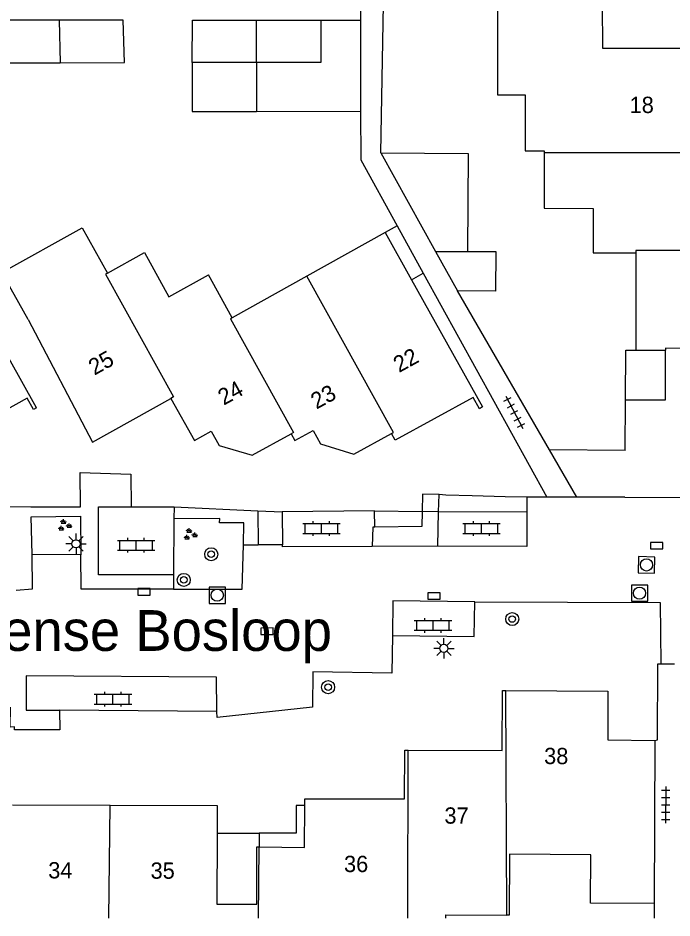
# Model space of a CAD drawing. Extents: x 128999 to 131010, y 395498 to 399007.
# Drawn here: x 130734 to 130774.1, y 395500 to 395555.2 of the extents above; entities that cross this region are included whole.
import ezdxf

# ---------------------------------------------------------------- set-up
doc = ezdxf.new("R2010")
doc.units = 0
for name, color, linetype in [('gg-afsc-erfafscheiding', 7, 'Continuous'), ('gg-anno-huisnummerreeks BGT', 7, 'Continuous'), ('gg-anno-openbare ruimte label', 7, 'Continuous'), ('gg-bbg-gedigitaliseerde bebouwing', 7, 'Continuous'), ('gg-bbg-gedigitaliseerde bijgebouw', 7, 'Continuous'), ('gg-bbg-hoofdgebouw', 7, 'Continuous'), ('gg-bbg-luifel en loopbrug', 7, 'Continuous'), ('gg-bbg-tussenscheiding', 7, 'Continuous'), ('gg-knt-verharding', 7, 'Continuous'), ('gg-knt-verharding nz', 7, 'Continuous'), ('gt-grn-groengrens', 7, 'Continuous'), ('gt-grn-weggrens', 7, 'Continuous'), ('gt-symb-boom', 7, 'Continuous'), ('gt-symb-groenvak', 7, 'Continuous'), ('gt-symb-klinker verharding', 7, 'Continuous'), ('gt-symb-kolk', 7, 'Continuous'), ('gt-symb-lichtmast', 7, 'Continuous'), ('gt-symb-rioolschacht', 7, 'Continuous'), ('gt-symb-tegel verharding', 7, 'Continuous')]:
    doc.layers.add(name, color=color, linetype=linetype)

# ---------------------------------------------------------------- blocks, each defined once
blk = doc.blocks.new('gt0-GRVAK')
at = {"layer": 'gt-symb-groenvak'}
for p, q in [((-0.11, 0.189), (-0.228, 0.24)), ((-0.182, 0.153), (0.088, 0.153)), ((-0.091, 0.211), (-0.156, 0.322)), ((-0.047, 0.214), (-0.047, 0.393)), ((-0.004, 0.211), (0.061, 0.322)), ((0.015, 0.189), (0.133, 0.24)), ((0.262, -0.052), (0.197, 0.059)), ((0.305, -0.049), (0.305, 0.13)), ((0.349, -0.052), (0.414, 0.059)), ((-0.245, -0.228), (-0.363, -0.177)), ((-0.318, -0.264), (-0.047, -0.264)), ((-0.226, -0.206), (-0.291, -0.095)), ((-0.183, -0.203), (-0.183, -0.024)), ((-0.139, -0.206), (-0.074, -0.095)), ((-0.12, -0.228), (-0.002, -0.177)), ((0.243, -0.074), (0.125, -0.023)), ((0.17, -0.11), (0.441, -0.11)), ((0.368, -0.074), (0.486, -0.023))]:
    blk.add_line(p, q, dxfattribs=at)
blk = doc.blocks.new('gt0-LMAST')
at = {"layer": 'gt-symb-lichtmast'}
for p, q in [((-0.005, 0.246), (-0.005, 0.621)), ((-0.182, 0.173), (-0.447, 0.438)), ((0.172, 0.173), (0.437, 0.438)), ((-0.255, -0.004), (-0.63, -0.004)), ((-0.182, -0.181), (-0.447, -0.446)), ((-0.005, -0.254), (-0.005, -0.629)), ((0.437, -0.446), (0.172, -0.181)), ((0.245, -0.004), (0.62, -0.004))]:
    blk.add_line(p, q, dxfattribs=at)
blk.add_circle((-0.005, -0.004), 0.25, dxfattribs=at)
blk = doc.blocks.new('gt0-KOLK')
at = {"layer": 'gt-symb-kolk'}
blk.add_lwpolyline([(0, 0), (0.375, 0), (0.375, 0.4), (-0.375, 0.4), (-0.375, 0), (0, 0)], dxfattribs=at)
blk = doc.blocks.new('gt0-KL1')
at = {"layer": 'gt-symb-klinker verharding'}
for p, q in [((-1.15, 0.3), (1.15, 0.3)), ((-1, -0.3), (-1, 0.3)), ((-0.5, 0.3), (-0.5, 0.45)), ((0, -0.3), (0, 0.3)), ((0.5, 0.3), (0.5, 0.45)), ((1, -0.3), (1, 0.3)), ((-1.15, -0.3), (1.15, -0.3)), ((-0.5, -0.45), (-0.5, -0.3)), ((0.5, -0.45), (0.5, -0.3))]:
    blk.add_line(p, q, dxfattribs=at)
blk = doc.blocks.new('gt0-BOOM')
at = {"layer": 'gt-symb-boom'}
for radius in [0.4, 0.2]:
    blk.add_circle((0, 0), radius, dxfattribs=at)
blk = doc.blocks.new('gt0-TEG1')
at = {"layer": 'gt-symb-tegel verharding'}
for p, q in [((-1.125, 0), (1.125, 0)), ((-0.9, -0.25), (-0.9, 0.25)), ((-0.45, -0.25), (-0.45, 0.25)), ((0, -0.25), (0, 0.25)), ((0.45, -0.25), (0.45, 0.25)), ((0.9, -0.25), (0.9, 0.25))]:
    blk.add_line(p, q, dxfattribs=at)
blk = doc.blocks.new('gt0-RS')
at = {"layer": 'gt-symb-rioolschacht'}
blk.add_lwpolyline([(-0.5, -0.5), (0.5, -0.5), (0.5, 0.5), (-0.5, 0.5)], close=True, dxfattribs=at)
blk.add_circle((0, 0), 0.375, dxfattribs=at)

msp = doc.modelspace()

# ---------------------------------------------------------------- linework, layer by layer
at = {"layer": 'gg-afsc-erfafscheiding'}
msp.add_line((130773.057, 395500.9), (130773.06, 395500), dxfattribs=at)
at = {"layer": 'gg-bbg-gedigitaliseerde bebouwing'}
for p, q in [((130756.528, 395542.083), (130751.719, 395539.402)), ((130771.93, 395540.82), (130771.92, 395534.85)), ((130743.235, 395538.128), (130745.68, 395539.48)), ((130747.13, 395536.844), (130745.68, 395539.48)), ((130751.719, 395539.402), (130747.13, 395536.844)), ((130734.59, 395536.73), (130738.546, 395529.209)), ((130771.92, 395534.85), (130773.75, 395534.85)), ((130771.265, 395528.694), (130771.29, 395531.81)), ((130768.295, 395525.828), (130766.615, 395528.732)), ((130771.265, 395528.694), (130766.615, 395528.732)), ((130771.241, 395525.822), (130768.295, 395525.828)), ((130773.057, 395500.9), (130769.14, 395500.91))]:
    msp.add_line(p, q, dxfattribs=at)
for points in [[(130769.881, 395556.118), (130763.43, 395556.12), (130763.42, 395550.52), (130765.12, 395550.52)], [(130765.12, 395550.52), (130765.12, 395547.09), (130766.29, 395547.09), (130766.29, 395546.97)], [(130766.29, 395546.97), (130766.29, 395543.56), (130769.31, 395543.55), (130769.31, 395540.83), (130771.93, 395540.82)], [(130734.59, 395536.73), (130732.981, 395539.611), (130737.908, 395542.363), (130739.46, 395539.583)], [(130735.104, 395531.313), (130729.403, 395541.529), (130724.626, 395538.852)], [(130739.46, 395539.583), (130741.735, 395540.841), (130743.235, 395538.128)], [(130771.29, 395531.81), (130773.74, 395531.8), (130773.75, 395534.85)], [(130769.14, 395500.91), (130769.16, 395503.88), (130764.17, 395503.91), (130764.15, 395500.18), (130763.99, 395500.181)], [(130760.259, 395500), (130760.26, 395500.2), (130763.99, 395500.181)]]:
    msp.add_lwpolyline(points, dxfattribs=at)
at = {"layer": 'gg-bbg-gedigitaliseerde bijgebouw'}
for p, q in [((130748.62, 395555.105), (130752.57, 395555.11)), ((130748.62, 395552.505), (130744.67, 395552.5)), ((130756.26, 395546.96), (130759.625, 395540.908)), ((130759.625, 395540.908), (130760.97, 395538.49))]:
    msp.add_line(p, q, dxfattribs=at)
for points in [[(130736.49, 395555.1), (130732.62, 395555.1), (130732.61, 395552.49), (130736.57, 395552.495)], [(130736.57, 395552.495), (130740.52, 395552.5), (130740.44, 395555.1), (130736.49, 395555.1)], [(130744.67, 395552.5), (130744.68, 395555.1), (130748.62, 395555.105)], [(130752.57, 395555.11), (130752.57, 395552.51), (130748.62, 395552.505)], [(130756.26, 395546.96), (130761.62, 395546.92), (130761.58, 395540.909)], [(130761.58, 395540.909), (130763.32, 395540.9), (130763.3, 395538.47), (130760.97, 395538.49)]]:
    msp.add_lwpolyline(points, dxfattribs=at)
at = {"layer": 'gg-bbg-hoofdgebouw'}
for p, q in [((130756.528, 395542.083), (130758.148, 395539.178)), ((130738.546, 395529.209), (130743.354, 395531.894)), ((130771.241, 395525.822), (130778.39, 395525.811)), ((130773.082, 395510.887), (130773.057, 395500.9)), ((130733.63, 395506.937), (130739.64, 395506.918))]:
    msp.add_line(p, q, dxfattribs=at)
for points in [[(130776.336, 395547.044), (130776.298, 395553.373), (130769.889, 395553.36), (130769.881, 395556.118)], [(130758.148, 395539.178), (130762.503, 395531.365), (130762.314, 395531.26), (130761.93, 395531.951), (130757.139, 395529.324), (130756.909, 395529.734)], [(130735.104, 395531.313), (130734.916, 395531.208), (130734.526, 395531.907), (130729.786, 395529.267), (130728.343, 395531.89)], [(130743.354, 395531.894), (130744.809, 395529.31), (130745.846, 395529.886), (130746.327, 395529.008), (130748.363, 395528.414), (130750.753, 395529.724)], [(130750.753, 395529.724), (130750.986, 395529.307), (130752.104, 395529.927), (130752.556, 395529.103), (130754.594, 395528.465), (130756.909, 395529.734)], [(130757.93, 395510.305), (130763.71, 395510.273), (130763.731, 395513.962), (130763.946, 395513.961)], [(130763.946, 395513.961), (130770.196, 395513.926), (130770.211, 395510.944), (130773.082, 395510.887)], [(130751.596, 395506.897), (130751.599, 395507.324), (130757.718, 395507.313), (130757.735, 395510.306), (130757.93, 395510.305)], [(130739.64, 395506.918), (130746.205, 395506.897), (130746.2, 395505.206)], [(130748.78, 395504.362), (130751.58, 395504.331), (130751.596, 395506.897)], [(130746.2, 395505.206), (130746.187, 395500.851), (130748.643, 395500.85), (130748.641, 395504.364), (130748.78, 395504.362)]]:
    msp.add_lwpolyline(points, dxfattribs=at)
at = {"layer": 'gg-bbg-luifel en loopbrug'}
for p, q in [((130752.57, 395555.11), (130755.004, 395555.113)), ((130755.004, 395555.113), (130755.016, 395549.513)), ((130748.62, 395552.505), (130748.624, 395549.505)), ((130748.624, 395549.505), (130755.016, 395549.513)), ((130757.258, 395542.49), (130756.528, 395542.083)), ((130757.258, 395542.49), (130758.867, 395539.578)), ((130758.148, 395539.178), (130758.867, 395539.578)), ((130746.2, 395505.206), (130748.78, 395505.206)), ((130748.78, 395505.206), (130748.78, 395504.362))]:
    msp.add_line(p, q, dxfattribs=at)
for points in [[(130744.67, 395552.5), (130744.67, 395549.5), (130748.624, 395549.505)], [(130771.29, 395531.81), (130771.315, 395534.855), (130771.92, 395534.85)], [(130751.596, 395506.897), (130751.06, 395506.897), (130751.06, 395505.206), (130748.78, 395505.206)]]:
    msp.add_lwpolyline(points, dxfattribs=at)
at = {"layer": 'gg-bbg-tussenscheiding'}
for p, q in [((130736.49, 395555.1), (130736.57, 395552.495)), ((130748.62, 395552.505), (130748.62, 395555.105)), ((130759.625, 395540.908), (130761.58, 395540.909)), ((130763.99, 395500.181), (130763.946, 395513.961)), ((130757.922, 395500), (130757.93, 395510.305)), ((130739.557, 395500), (130739.64, 395506.918)), ((130748.743, 395500), (130748.78, 395504.362))]:
    msp.add_line(p, q, dxfattribs=at)
for points in [[(130776.336, 395547.044), (130776.336, 395546.964), (130766.29, 395546.97)], [(130779.061, 395541.041), (130779.061, 395540.961), (130771.93, 395540.975), (130771.93, 395540.82)], [(130739.46, 395539.583), (130739.351, 395539.523), (130743.518, 395531.986), (130743.354, 395531.894)], [(130756.909, 395529.734), (130757.046, 395529.809), (130751.719, 395539.402)], [(130747.13, 395536.844), (130747.02, 395536.783), (130750.888, 395529.798), (130750.753, 395529.724)], [(130781.906, 395535.039), (130781.906, 395534.964), (130773.75, 395534.969), (130773.75, 395534.85)]]:
    msp.add_lwpolyline(points, dxfattribs=at)
at = {"layer": 'gg-knt-verharding'}
for p, q in [((130758.867, 395539.578), (130766.463, 395525.832)), ((130766.615, 395528.732), (130760.97, 395538.49)), ((130759.81, 395524.938), (130759.836, 395525.991)), ((130765.226, 395525.834), (130765.23, 395524.901)), ((130766.463, 395525.832), (130765.226, 395525.834)), ((130768.295, 395525.828), (130766.463, 395525.832)), ((130740.922, 395525.236), (130743.567, 395525.227)), ((130743.567, 395525.227), (130748.712, 395524.995)), ((130743.534, 395524.501), (130743.532, 395521.066)), ((130748.712, 395524.995), (130748.734, 395522.897)), ((130748.712, 395524.995), (130750.2, 395524.928)), ((130755.872, 395524.988), (130750.2, 395524.928)), ((130750.2, 395524.928), (130750.214, 395522.909)), ((130755.891, 395523.992), (130755.872, 395524.988)), ((130759.81, 395524.938), (130758.798, 395524.945)), ((130765.23, 395524.901), (130759.81, 395524.938)), ((130750.214, 395522.909), (130748.734, 395522.897)), ((130737.829, 395522.295), (130734.831, 395522.318)), ((130743.532, 395521.066), (130743.532, 395520.186)), ((130773.463, 395515.609), (130774.303, 395515.609)), ((130746.19, 395512.677), (130736.526, 395512.748))]:
    msp.add_line(p, q, dxfattribs=at)
for points in [[(130756.26, 395546.96), (130756.43, 395556.078), (130755.002, 395556.073), (130755.004, 395555.113)], [(130755.016, 395549.513), (130755.022, 395546.536), (130757.258, 395542.49)], [(130729.373, 395525.284), (130734.764, 395525.236), (130737.809, 395525.236), (130737.785, 395527.345), (130740.893, 395527.239), (130740.922, 395525.236)], [(130759.836, 395525.991), (130758.811, 395526.012), (130758.798, 395524.945)], [(130734.831, 395522.318), (130734.784, 395524.633), (130737.801, 395524.67), (130737.829, 395522.295)], [(130747.813, 395522.905), (130747.849, 395524.245), (130746.34, 395524.262), (130746.359, 395524.512), (130743.534, 395524.501)], [(130758.798, 395524.945), (130758.781, 395524.03), (130755.891, 395523.992)], [(130743.532, 395520.186), (130747.741, 395520.174), (130747.813, 395522.905)], [(130756.969, 395517.349), (130761.999, 395517.27), (130762.037, 395519.409)], [(130762.037, 395519.409), (130773.414, 395519.358), (130773.463, 395515.609)], [(130756.969, 395517.349), (130756.945, 395515.029), (130752.076, 395515.1), (130752.062, 395512.942), (130746.215, 395512.303), (130746.19, 395512.677)], [(130773.082, 395510.887), (130773.245, 395510.93), (130773.277, 395515.609), (130773.463, 395515.609)], [(130736.526, 395512.748), (130736.531, 395511.559), (130733.761, 395511.547), (130733.761, 395511.727), (130733.479, 395511.717), (130733.518, 395512.931)]]:
    msp.add_lwpolyline(points, dxfattribs=at)
at = {"layer": 'gg-knt-verharding nz'}
for p, q in [((130743.567, 395525.227), (130743.534, 395524.501)), ((130759.77, 395522.817), (130759.81, 395524.938))]:
    msp.add_line(p, q, dxfattribs=at)
for points in [[(130743.532, 395521.066), (130738.916, 395521.064), (130738.92, 395525.236), (130740.922, 395525.236)], [(130765.23, 395524.901), (130765.226, 395522.805), (130759.77, 395522.817)], [(130755.891, 395523.992), (130755.773, 395523.99), (130755.73, 395522.808)], [(130755.73, 395522.808), (130750.215, 395522.782), (130750.214, 395522.909)], [(130762.037, 395519.409), (130757.006, 395519.47), (130756.969, 395517.349)], [(130746.19, 395512.677), (130746.169, 395514.772), (130734.476, 395514.871), (130734.462, 395512.763), (130736.526, 395512.748)]]:
    msp.add_lwpolyline(points, dxfattribs=at)
at = {"layer": 'gt-grn-groengrens'}
msp.add_line((130755.872, 395524.988), (130758.798, 395524.945), dxfattribs=at)
msp.add_lwpolyline([(130765.226, 395525.834), (130763.896, 395525.851), (130761.866, 395525.919), (130760.245, 395525.949), (130759.836, 395525.991)], dxfattribs=at)
at = {"layer": 'gt-grn-weggrens'}
for p, q in [((130747.813, 395522.905), (130748.734, 395522.897)), ((130759.77, 395522.817), (130755.73, 395522.808))]:
    msp.add_line(p, q, dxfattribs=at)
for points in [[(130733.849, 395520.129), (130734.859, 395520.195), (130734.831, 395522.318)], [(130743.532, 395520.186), (130737.844, 395520.181), (130737.829, 395522.295)]]:
    msp.add_lwpolyline(points, dxfattribs=at)

# ---------------------------------------------------------------- block references
at = {"layer": 'gt-symb-boom'}
for p in [(130745.838, 395522.329), (130744.154, 395520.752), (130764.331, 395518.35), (130753.019, 395514.168)]:
    msp.add_blockref('gt0-BOOM', p, dxfattribs=at)
at = {"layer": 'gt-symb-groenvak'}
for p in [(130736.814, 395524.09), (130744.531, 395523.536)]:
    msp.add_blockref('gt0-GRVAK', p, dxfattribs=at)
at = {"layer": 'gt-symb-klinker verharding'}
for p in [(130752.61, 395523.909), (130762.442, 395523.909), (130741.226, 395522.874), (130759.466, 395517.958), (130739.803, 395513.43)]:
    msp.add_blockref('gt0-KL1', p, dxfattribs=at)
at = {"layer": 'gt-symb-kolk'}
for p in [(130773.201, 395522.649), (130741.705, 395519.819), (130759.524, 395519.566)]:
    msp.add_blockref('gt0-KOLK', p, dxfattribs=at)
at = {"layer": 'gt-symb-kolk', "rotation": 0.11459140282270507}
msp.add_blockref('gt0-KOLK', (130749.272, 395517.399), dxfattribs=at)
at = {"layer": 'gt-symb-lichtmast'}
for p in [(130737.541, 395522.971), (130760.139, 395516.553)]:
    msp.add_blockref('gt0-LMAST', p, dxfattribs=at)
at = {"layer": 'gt-symb-rioolschacht', "rotation": 178.22439947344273}
msp.add_blockref('gt0-RS', (130772.582, 395521.673), dxfattribs=at)
at = {"layer": 'gt-symb-rioolschacht'}
for p in [(130746.211, 395519.813), (130772.152, 395519.938)]:
    msp.add_blockref('gt0-RS', p, dxfattribs=at)
at = {"layer": 'gt-symb-tegel verharding'}
for p, rotation in [((130764.461, 395531.034), -62.64135830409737), ((130773.758, 395506.94), -90.17188682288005)]:
    msp.add_blockref('gt0-TEG1', p, dxfattribs=dict(at, rotation=rotation))

# ---------------------------------------------------------------- texts
at = {"layer": 'gg-anno-huisnummerreeks BGT'}
for s, rotation, p in [('18', 0.3, (130771.545, 395549.403)), ('22', 28.7, (130757.379, 395533.448)), ('25', 29.2, (130738.664, 395533.284)), ('24', 28.7, (130746.606, 395531.443)), ('23', 28.7, (130752.306, 395531.203)), ('38', 359.7, (130766.287, 395509.447)), ('37', 359.7, (130760.164, 395505.792)), ('36', 359.9, (130753.996, 395502.819)), ('34', 359.8, (130735.826, 395502.431)), ('35', 359.8, (130742.113, 395502.411))]:
    msp.add_text(s, height=1, rotation=rotation, dxfattribs=at).set_placement(p)
at = {"layer": 'gg-anno-openbare ruimte label'}
msp.add_text('Calfvense Bosloop', height=2.5, dxfattribs=at).set_placement((130725.382, 395516.395))

doc.saveas('drawing.dxf')
